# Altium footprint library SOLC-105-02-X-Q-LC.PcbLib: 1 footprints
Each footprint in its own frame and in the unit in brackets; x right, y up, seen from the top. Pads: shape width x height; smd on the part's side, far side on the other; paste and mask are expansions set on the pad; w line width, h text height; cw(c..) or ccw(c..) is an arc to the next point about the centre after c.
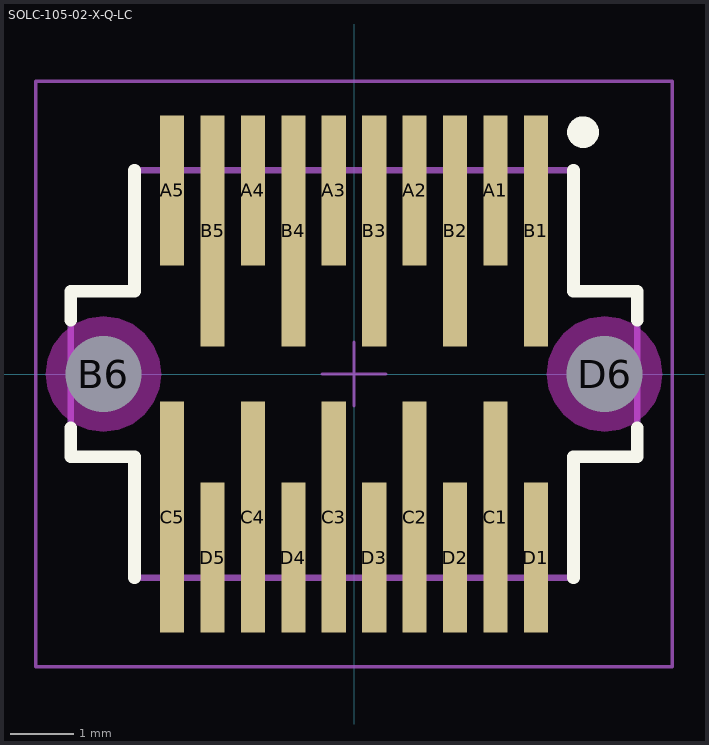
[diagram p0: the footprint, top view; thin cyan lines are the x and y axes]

## SOLC-105-02-X-Q-LC [mm] "1.27mm pitch, 20 pin, socket strip; 4 rows, w/locking clips, SMT"
height 4.62
pads (22):
  rect 0.38x2.36 smd mask+0: A1(2.222,2.885) A2(0.953,2.885) A3(-0.318,2.885) A4(-1.587,2.885) A5(-2.857,2.885) D1(2.857,-2.885) D2(1.587,-2.885) D3(0.318,-2.885) D4(-0.953,-2.885) D5(-2.222,-2.885)
  rect 0.38x3.63 smd mask+0: B1(2.857,2.25) B2(1.587,2.25) B3(0.318,2.25) B4(-0.953,2.25) B5(-2.222,2.25) C1(2.222,-2.25) C2(0.953,-2.25) C3(-0.318,-2.25) C4(-1.587,-2.25) C5(-2.857,-2.25)
  round 1 hole 1.19 unplated mask+0: B6(-3.937,0) D6(3.937,0)
Top Overlay:
  circle w0.25: c3.6,3.8 r0.125
  lines w0.2: -4.45,-0.85 -4.45,-1.3 -3.45,-1.3 -3.45,-3.2 ; -4.45,0.85 -4.45,1.3 -3.45,1.3 -3.45,3.2 ; 3.45,-3.2 3.45,-1.3 4.45,-1.3 4.45,-0.85 ; 3.45,3.2 3.45,1.3 4.45,1.3 4.45,0.85
Keep-Out Layer:
  pour cut-out: 4.845,0 4.814,0.235 4.723,0.454 4.579,0.642 4.391,0.786 4.172,0.877 3.937,0.908 3.702,0.877 3.483,0.786 3.295,0.642 3.151,0.454 3.06,0.235 3.029,0 3.06,-0.235 3.151,-0.454 3.295,-0.642 3.483,-0.786 3.702,-0.877 3.937,-0.908 4.172,-0.877 4.391,-0.786 4.579,-0.642 4.723,-0.454 4.814,-0.235
  pour cut-out: -3.029,0 -3.06,0.235 -3.151,0.454 -3.295,0.642 -3.483,0.786 -3.702,0.877 -3.937,0.908 -4.172,0.877 -4.391,0.786 -4.579,0.642 -4.723,0.454 -4.814,0.235 -4.845,0 -4.814,-0.235 -4.723,-0.454 -4.579,-0.642 -4.391,-0.786 -4.172,-0.877 -3.937,-0.908 -3.702,-0.877 -3.483,-0.786 -3.295,-0.642 -3.151,-0.454 -3.06,-0.235
Mechanical 12:
  lines w0.001: -4.45,-1.3 -4.45,1.3 -3.45,1.3 -3.45,3.2 3.45,3.2 3.45,1.3 4.45,1.3 4.45,-1.3 3.45,-1.3 3.45,-3.2 -3.45,-3.2 -3.45,-1.3 -4.45,-1.3
Mechanical 13:
  lines w0.1: -4.45,-1.3 -4.45,1.3 -3.45,1.3 -3.45,3.2 3.45,3.2 3.45,1.3 4.45,1.3 4.45,-1.3 3.45,-1.3 3.45,-3.2 -3.45,-3.2 -3.45,-1.3 -4.45,-1.3
  text ".Designator" at 0,-0.127 h1.52
Mechanical 15:
  lines w0.05: -0.5,0 0.5,0 ; 0,-0.5 0,0.5 ; -5,-4.6 -5,4.6 5,4.6 5,-4.6 -5,-4.6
